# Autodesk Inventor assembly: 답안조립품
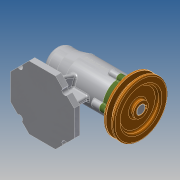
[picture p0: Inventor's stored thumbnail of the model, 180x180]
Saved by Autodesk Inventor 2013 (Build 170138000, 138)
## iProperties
Created: 2019-12
Part Number: 답안조립품
Document SubType Name: Assembly
Designer: Administrator
Author: Administrator
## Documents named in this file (12)
- C:\Users\Administrator\Desktop\491204V1023\답안조립품.iam
- C:\Users\Administrator\Desktop\491204V1023\답안본체.ipt
- C:\Users\Administrator\Desktop\491204V1023\491204V1023\V벨트풀리.ipt
- C:\Users\Administrator\Desktop\491204V1023\491204V1023\멈춤나사 M3.ipt
- C:\Users\Administrator\Desktop\491204V1023\491204V1023\베어링 6004.ipt
- C:\Users\Administrator\Desktop\491204V1023\491204V1023\베어링 51202.ipt
- C:\Users\Administrator\Desktop\491204V1023\491204V1023\볼트 M4.ipt
- C:\Users\Administrator\Desktop\491204V1023\491204V1023\어댑터슬리브.ipt
- C:\Users\Administrator\Desktop\491204V1023\491204V1023\오일 실.ipt
- C:\Users\Administrator\Desktop\491204V1023\491204V1023\축.ipt
- C:\Users\Administrator\Desktop\491204V1023\491204V1023\커버.ipt
- C:\Users\Administrator\Desktop\491204V1023\491204V1023\키 5 x 5 x 16.ipt
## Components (1 placed, 1 different names)
1. V벨트풀리:1
